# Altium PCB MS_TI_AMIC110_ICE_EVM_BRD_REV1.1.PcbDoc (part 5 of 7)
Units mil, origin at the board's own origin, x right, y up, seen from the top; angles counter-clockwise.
Board outline 3464.57 x 2204.72 mil, 8 copper layers (TopLayer - S1 (.GTL), MidLayer1 - S2 (.G1), MidLayer2 - S3 (.G2), MidLayer3 - S4 (.G3), MidLayer4 - S5 (.G4), MidLayer5 - S6 (.G5), MidLayer6 - S7 (.G6), BottomLayer - S8 (.GBL)), stack 58.937 mil thick; 504 components, 369 nets, 1811 pads, 874 vias.
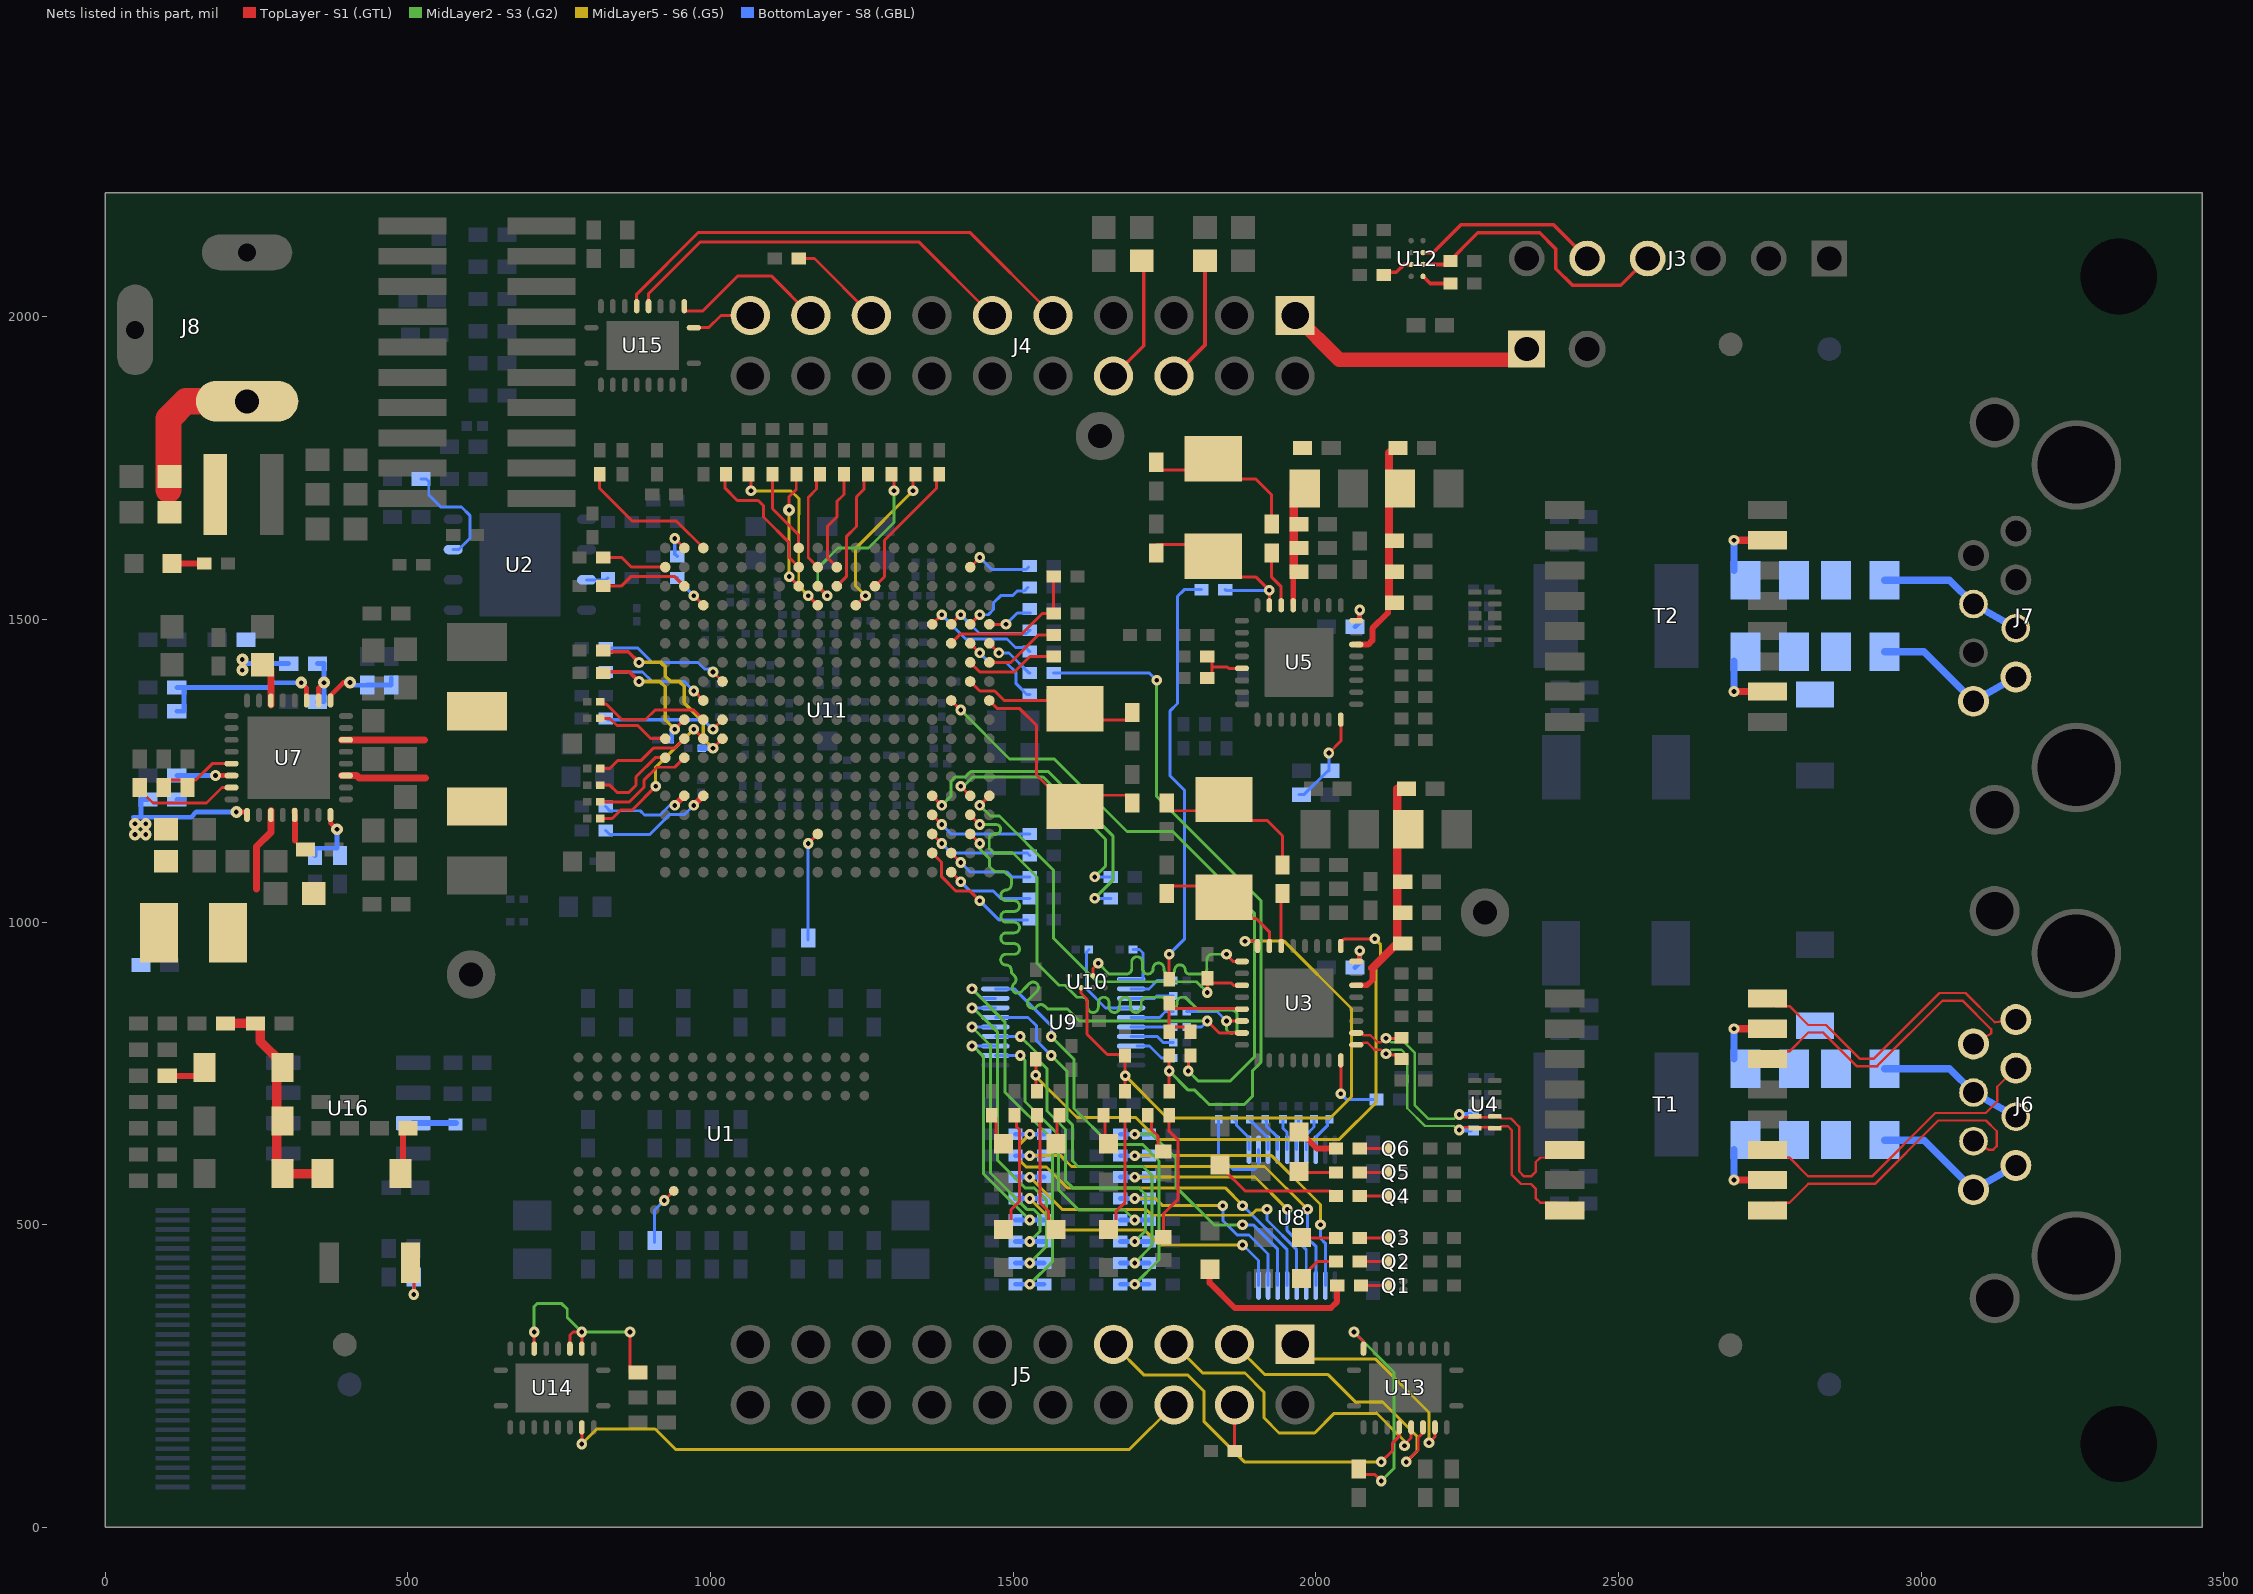
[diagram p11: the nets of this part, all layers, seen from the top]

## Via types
v1: diameter 17.72, hole 7.87, TopLayer - S1 (.GTL) to BottomLayer - S8 (.GBL), 746 vias
v2: diameter 19.68, hole 7.87, TopLayer - S1 (.GTL) to BottomLayer - S8 (.GBL), 128 vias

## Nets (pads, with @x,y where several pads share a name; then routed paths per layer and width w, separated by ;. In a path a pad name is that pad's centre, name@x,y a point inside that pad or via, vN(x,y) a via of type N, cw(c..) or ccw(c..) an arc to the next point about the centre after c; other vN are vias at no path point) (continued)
NetC36_1: C36.1 C37.1 C38.1 C39.1 R46.1 U3.14 | length 378.1
  TopLayer - S1 (.GTL) w9.45: U3.14@2066.93,895.67 2084.65,895.67 2093.5,904.53
  TopLayer - S1 (.GTL) w10: 2093.5,904.53 2093.5,924.21
  TopLayer - S1 (.GTL) w13.78: 2093.5,924.21 2134.84,965.55 2134.84,1015.75 2134.84,1220.47 R46.1@2149.61,1220.47
NetC45_1: C45.1 R50.2 Y1.1 | length 246.8
  TopLayer - S1 (.GTL) w4.92: C45.1@1753.94,1196.85 1753.94,1184.06 Y1.1@1839.57,1184.06 ; Y1.1@1848.43,1202.76 Y1.1@1858.27,1202.76 ; Y1.1@1865.16,1168.31 1919.29,1168.31 1944.88,1142.72 R50.2@1944.88,1094.49
NetC46_1: C46.1 U3.23 Y1.2 | length 232.4
  TopLayer - S1 (.GTL) w4.92: C46.1@1747.05,1060.04 Y1.2@1876.97,1060.04 ; Y1.2@1848.43,1041.34 Y1.2@1860.24,1041.34 ; Y1.2@1865.16,1005.91 1901.57,1005.91 1923.23,984.25 U3.23@1923.23,960.63
NetC55_1: C55.1 C56.1 C57.1 C58.1 R57.1 U5.21 | length 207
  TopLayer - S1 (.GTL) w9.45: U5.21@1962.6,1523.62 1962.6,1565.94
  TopLayer - S1 (.GTL) w13.78: C58.1@1972.44,1574.8 1963.58,1574.8 1963.58,1712.6 C55.1@1981.65,1712.6
NetC63_1: C63.1 C64.1 C65.1 C66.1 R62.1 U5.14 | length 363.4
  TopLayer - S1 (.GTL) w10: U5.14@2066.93,1458.66 2086.61,1458.66 2093.5,1465.55 2093.5,1485.24 2119.09,1510.83 2119.09,1516.73 C66.1@2129.92,1527.56
  TopLayer - S1 (.GTL) w13.78: R62.1@2121.06,1775.59 2121.06,1527.56 C66.1@2129.92,1527.56
NetC68_1: C68.1 R70.2 Y2.1 | length 264
  TopLayer - S1 (.GTL) w4.92: C68.1@1736.22,1759.84 1736.22,1747.05 Y2.1@1821.85,1747.05 ; Y2.1@1830.71,1765.75 Y2.1@1864.67,1731.79 ; Y2.1@1868.6,1731.79 1901.08,1731.79 1927.17,1705.71 R70.2@1927.17,1657.48
NetC69_2: C69.2 R74.1 U5.23 Y2.2 | length 374.7
  TopLayer - S1 (.GTL) w4.92: C69.2@1736.22,1610.24 1736.22,1623.72 1858.56,1623.72 Y2.2@1859.25,1623.03 ; Y2.2@1843.5,1604.33 Y2.2@1830.71,1604.33 1845.47,1589.57 1845.47,1569.88 1901.57,1569.88 v1(1923.23,1548.23) U5.23@1923.23,1523.62
  BottomLayer - S8 (.GBL) w4.92: R74.1@1850.39,1549.21 1851.38,1548.23 v1(1923.23,1548.23)
NetC72_2: C72.2 R80.2 U7.29 | length 48.9
  TopLayer - S1 (.GTL) w10: U7.29@312.99,1184.06 313.44,1174.5 313.44,1135.34 313.31,1135.22
NetC74_1: C74.1 C75.1 L2.2 R81.1 R82.2 U7.25 | length 232
  TopLayer - S1 (.GTL) w7.87: v2(216.54,1182.09) U7.25@233.27,1182.09
  BottomLayer - S8 (.GBL) w7.87: 46.26,1173.23 59.06,1173.23 ; R82.2@70.87,1202.76 59.06,1202.76 59.06,1173.23 ; v2(216.54,1182.09) 150.59,1182.09 141.73,1173.23 59.06,1173.23
  other v2: 49.21,1144.68 66.93,1144.68 49.21,1162.4 66.93,1162.4
NetC76_1: C76.1 D11.2 D12.1 D13.1 D14.1 R83.1 | length 386.4
  TopLayer - S1 (.GTL) w15.75: C76.1@198.82,832.68 R83.1@248.03,832.68 255.91,832.68 255.91,803.15 292.82,766.24 D12.1@292.82,759.84 D12.1@292.82,746.06 ; D14.1@282.97,581.69 D13.1@282.97,668.31 ; D13.1@282.97,671.26 D12.1@282.97,746.06 ; D14.1@292.82,584.65 D11.2@358.76,584.65
NetC87_1: C87.1 R98.1 R99.2 U7.14 | length 130.9
  TopLayer - S1 (.GTL) w11.81: U7.14@273.62,1359.25 U7.14@273.62,1366.14 C87.1@273.62,1419.29
  BottomLayer - S8 (.GBL) w7.87: v2@232.28,1427.17 R99.2@303.15,1427.17
  other v2: 226.38,1416.34 226.38,1434.06
NetC131_1: C131.1 U11.D9 | length 202
  TopLayer - S1 (.GTL) w4.92: v1(1003.94,1318.9) U11.D9@1019.68,1334.65
  BottomLayer - S8 (.GBL) w5.91: C131.1@830.71,1334.65 988.19,1334.65 v1(1003.94,1318.9)
NetC132_1: C132.1 U11.D11 | length 211.8
  TopLayer - S1 (.GTL) w4.92: v1(1003.94,1413.39) U11.D11@1019.68,1397.64
  BottomLayer - S8 (.GBL) w4.92: C132.1@830.71,1452.76 879.92,1452.76 903.54,1429.13 979.33,1429.13 990.16,1418.31 v1@999.02,1418.31
  BottomLayer - S8 (.GBL) w5.91: v1@999.02,1418.31 v1(1003.94,1413.39)
NetC133_1: C133.1 U11.C10 | length 176.4
  TopLayer - S1 (.GTL) w4.92: v1@972.92,1381.42 U11.C10@988.19,1366.14
  BottomLayer - S8 (.GBL) w4.92: C133.1@830.71,1413.39 887.8,1413.39 903.54,1397.64 956.69,1397.64 v1(972.44,1381.89)
NetC168_1: C168.1 U11.V10 Y3.2 | length 366.5
  TopLayer - S1 (.GTL) w4.92: U11.V10@1460.63,1366.14 1473.43,1353.35 1510.22,1353.35 1538.39,1325.18 1538.39,1243.11 1563.98,1217.52 Y3.2@1573.82,1217.52 ; Y3.2@1573.82,1209.65 C168.1@1696.85,1209.65 ; C168.1@1696.85,1196.85 C168.1@1696.85,1209.65 ; C168.1@1704.72,1209.65 C168.1@1696.85,1209.65
NetC170_1: C170.1 U11.U11 Y3.1 | length 307
  TopLayer - S1 (.GTL) w4.92: U11.U11@1429.13,1397.64 1444.88,1381.89 1469.49,1381.89 1485.24,1366.14 1588.58,1366.14 Y3.1@1602.36,1352.36 1621.06,1333.66 1696.85,1333.66 C170.1@1696.85,1346.46
NetC177_1: C177.1 C178.1 J8.1 L4.1 | length 259
  TopLayer - S1 (.GTL) w43.31: 104.33,1714.57 104.33,1831.69 133.21,1860.57 J8.1@234.25,1860.57
NetC182_1: C182.1 R182.2 U11.D8 | length 338.3
  TopLayer - S1 (.GTL) w4.92: v1(1003.95,1287.4) U11.D8@1019.68,1303.15
  TopLayer - S1 (.GTL) w5.91: R182.2@815.94,1446.85 864.17,1446.85 v1(881.89,1429.13)
  MidLayer5 - S6 (.G5) w5.91: v1(881.89,1429.13) 918.31,1429.13 925.2,1422.24 925.2,1406.5 934.06,1397.64 948.82,1397.64 956.69,1389.76 956.69,1362.2 988.19,1330.71 988.19,1303.16 v1(1003.95,1287.4)
  BottomLayer - S8 (.GBL) w9.84: C182.1@983.46,1287.4 C182.1@985.43,1287.4 v1(1003.95,1287.4)
NetC183_1: C183.1 R183.1 U11.B9 | length 230.7
  TopLayer - S1 (.GTL) w4.92: v1(940.94,1318.9) U11.B9@956.69,1334.65
  TopLayer - S1 (.GTL) w5.91: R183.1@822.83,1413.39 866.14,1413.39 v1(881.89,1397.64)
  MidLayer5 - S6 (.G5) w5.91: v1(881.89,1397.64) 916.34,1397.64 925.2,1388.78 925.2,1334.65 v1(940.94,1318.9)
  BottomLayer - S8 (.GBL) w7.87: C183.1@936.02,1299.21 v1@936.02,1318.7
NetC184_1: C184.1 R220.1 R221.1 R222.1 R223.1
NetC186_1: C186.1 R224.1 R225.1 R226.1 R227.1
NetD2_2: D2.2 R19.1 | length 203.7
  TopLayer - S1 (.GTL) w4.92: D2.2@1484.25,492.13 1496.06,503.94 1496.06,524.61 1510.83,539.37 1510.83,656.5 1505.91,661.42 1505.91,677.17 R19.1@1501.97,681.1
NetD3_2: D3.2 R20.1 | length 202.8
  TopLayer - S1 (.GTL) w4.92: R20.1@1537.4,681.1 1544.29,674.21 1544.29,536.42 1558.07,522.64 1558.07,504.92 D3.2@1570.87,492.13
NetD4_2: D4.2 R21.1 | length 200.4
  TopLayer - S1 (.GTL) w4.92: D4.2@1657.48,492.13 1670.28,504.92 1670.28,522.64 1685.04,537.4 R21.1@1685.04,681.1
NetD5_1: D5.1 R22.1 | length 218.1
  TopLayer - S1 (.GTL) w4.92: D5.1@1748.03,479.33 1748.03,517.72 1772.64,542.32 1772.64,639.76 1757.87,654.53 R22.1@1757.87,681.1
NetD6_1: D6.1 R26.1 | length 62.1
  TopLayer - S1 (.GTL) w4.92: D6.1@1972.19,588.51 1974.09,586.61 R26.1@2033.46,586.61
NetD7_2: D7.2 R28.2 | length 54.6
  TopLayer - S1 (.GTL) w4.92: R28.2@1466.54,681.1 1471.46,676.18 1471.46,646.65 D7.2@1484.25,633.86
NetD8_2: D8.2 R29.1 | length 48.1
  TopLayer - S1 (.GTL) w4.92: D8.2@1570.87,633.86 1572.83,635.83 R29.1@1572.83,681.1
NetD9_2: D9.2 R30.1 | length 49.7
  TopLayer - S1 (.GTL) w4.92: R30.1@1651.57,681.1 1651.57,639.76 D9.2@1657.48,633.86
NetD10_1: D10.1 R31.1 | length 70.6
  TopLayer - S1 (.GTL) w4.92: R31.1@1722.44,681.1 1728.35,675.2 1728.35,657.48 1739.17,646.65 1739.17,629.92 D10.1@1748.03,621.06
NetD11_1: D11.1 R84.1 | length 87.1
  TopLayer - S1 (.GTL) w9.84: D11.1@487.7,584.65 492.13,584.65 492.13,659.45 R84.1@500,659.45
NetD12_2: D12.2 R88.1 | length 75.3
  TopLayer - S1 (.GTL) w9.84: R88.1@102.36,746.06 163.88,746.06 D12.2@163.88,759.84
NetD15_2: D15.2 R178.1 | length 47.2
  TopLayer - S1 (.GTL) w9.84: D15.2@116.14,1592.52 R178.1@163.39,1592.52
NetD16_1: D16.1 R15.1 | length 281.3
  TopLayer - S1 (.GTL) w9.84: D16.1@1824.6,426.53 1824.6,404.12 1866.23,362.5 2024.86,362.5 2035.28,372.93 R15.1@2035.28,399.56
NetD17_1: D17.1 R16.1 | length 67.7
  TopLayer - S1 (.GTL) w4.92: D17.1@1976.5,412.95 2002.53,438.98 R16.1@2033.46,438.98
NetD18_1: D18.1 R17.1 | length 61.9
  TopLayer - S1 (.GTL) w4.92: D18.1@1971.97,479.43 1973.06,478.35 R17.1@2033.46,478.35
NetD19_1: D19.1 R25.1 | length 207.1
  TopLayer - S1 (.GTL) w4.92: D19.1@1845.54,593.5 1883.02,556.01 2024.7,556.01 R25.1@2033.46,547.24
NetD20_1: D20.1 R27.1 | length 72.6
  TopLayer - S1 (.GTL) w9.84: D20.1@1972.88,654.92 2001.81,625.98 R27.1@2033.46,625.98
NetJ3_4: J3.4 R172.2 U12.B1 | length 466.1
  TopLayer - S1 (.GTL) w5.91: U12.B1@2177.17,2086.61 2215.55,2086.61 2267.72,2138.78 2370.08,2138.78 2396.65,2112.2 2396.65,2079.72 2424.21,2052.17 2504.13,2052.17 J3.4@2548.43,2096.46
NetJ3_5: J3.5 U12.C1 | length 313.7
  TopLayer - S1 (.GTL) w5.91: U12.C1@2177.17,2106.3 2193.9,2106.3 2240.16,2152.56 2392.32,2152.56 J3.5@2448.43,2096.46
NetJ4_1: J4.1 J9.1 | length 420.3
  TopLayer - S1 (.GTL) w23.62: J4.1@1965.75,2002.36 2038.98,1929.13 2330.71,1929.13 J9.1@2348.43,1946.85
NetJ4_6: J4.6 R180.1 | length 211.4
  TopLayer - S1 (.GTL) w5.91: J4.6@1765.75,1902.36 1816.93,1953.54 R180.1@1816.93,2092.52
NetJ4_8: J4.8 R181.1 | length 212
  TopLayer - S1 (.GTL) w5.91: J4.8@1665.75,1902.36 1715.55,1952.17 1715.55,2089.57 R181.1@1712.6,2092.52
NetJ4_9: J4.9 U15.16 | length 806.8
  TopLayer - S1 (.GTL) w4.92: U15.16@877.95,2017.72 877.95,2037.4 980.31,2139.76 1428.35,2139.76 J4.9@1565.75,2002.36
NetJ4_11: J4.11 U15.15 | length 674.6
  TopLayer - S1 (.GTL) w4.92: U15.15@897.64,2017.72 897.64,2038.39 983.27,2124.02 1344.09,2124.02 J4.11@1465.75,2002.36
NetJ4_15: J4.15 R187.2 | length 159.1
  TopLayer - S1 (.GTL) w4.92: R187.2@1145.67,2096.46 1171.65,2096.46 J4.15@1265.75,2002.36
NetJ4_17: J4.17 U15.12 | length 268.1
  TopLayer - S1 (.GTL) w4.92: U15.12@956.69,2017.72 956.69,2009.84 987.2,2009.84 1045.28,2067.91 1100.2,2067.91 J4.17@1165.75,2002.36
NetJ4_19: J4.19 U15.11 | length 101.6
  TopLayer - S1 (.GTL) w4.92: U15.11@972.44,1982.28 997.05,1982.28 1017.13,2002.36 J4.19@1065.75,2002.36
NetJ5_1: J5.1 U13.18 | length 347.7
  TopLayer - S1 (.GTL) w4.92: v1(2187.01,139.76) 2196.85,149.61 U13.18@2196.85,165.35
  MidLayer5 - S6 (.G5) w4.92: J5.1@1965.75,302.36 1989.57,278.54 2098.43,278.54 2187.01,189.96 v1(2187.01,139.76)
NetJ5_3: J5.3 U13.17 | length 482.6
  TopLayer - S1 (.GTL) w4.92: v1(2149.61,108.27) 2169.29,127.95 2169.29,148.62 2177.17,156.5 U13.17@2177.17,165.35
  MidLayer5 - S6 (.G5) w4.92: J5.3@1865.75,302.36 1915.16,252.95 2019.69,252.95 2065.07,207.57 2110.34,207.57 2167.32,150.59 2167.32,125.98 v1(2149.61,108.27)
NetJ5_4: J5.4 R186.1 | length 100.2
  TopLayer - S1 (.GTL) w4.92: J5.4@1865.75,202.36 1865.75,126.38 R186.1@1866.14,125.98
  BottomLayer - S8 (.GBL) w4.92: J5.4@1865.75,178.74 J5.4@1865.75,202.36
NetJ5_5: J5.5 U13.16 | length 542.2
  TopLayer - S1 (.GTL) w4.92: v1(2146.72,134.71) 2146.72,136.88 2157.48,147.64 U13.16@2157.48,165.35
  MidLayer5 - S6 (.G5) w4.92: J5.5@1765.75,302.36 1813.19,254.92 1882.87,254.92 1914.37,223.43 1914.37,181.1 1939.32,156.15 1998.12,156.15 2030.45,188.48 2099.8,188.48 2100.19,188.87 2133.86,155.2 ; 2133.86,155.51 2146.72,142.65 v1(2146.72,134.71)
NetJ5_6: J5.6 U14.18 | length 1060.4
  TopLayer - S1 (.GTL) w4.68: v1(787.4,137.8) U14.18@787.4,165.35
  MidLayer5 - S6 (.G5) w4.92: v1(787.4,137.8) 812.01,162.4 908.46,162.4 941.93,128.94 1692.32,128.94 J5.6@1765.75,202.36
NetJ5_7: J5.7 U13.15 | length 621.6
  TopLayer - S1 (.GTL) w4.92: v1(2108.27,108.27) 2126.97,126.97 2126.97,139.76 2137.8,150.59 U13.15@2137.8,165.35
  MidLayer5 - S6 (.G5) w4.92: J5.7@1665.75,302.36 1716.54,251.57 1788.78,251.57 1814.96,225.39 1814.96,175.2 1881.89,108.27 v1(2108.27,108.27)
NetJ6_4: J6.4 J6.5 R220.2 | length 244.1
  BottomLayer - S8 (.GBL) w11.81: R220.2@2939.61,757.87 3047.24,757.87 J6.4@3086.61,718.5 J6.5@3156.69,678.35
NetJ6_7: J6.7 J6.8 R221.2 | length 261.7
  BottomLayer - S8 (.GBL) w11.81: R221.2@2939.61,639.76 3004.72,639.76 J6.8@3086.61,557.87 J6.7@3156.69,598.03
NetJ7_4: J7.4 J7.5 R224.2 | length 244.1
  BottomLayer - S8 (.GBL) w11.81: R224.2@2939.61,1564.96 3047.24,1564.96 J7.4@3086.61,1525.59 J7.5@3156.69,1485.43
NetJ7_7: J7.7 J7.8 R225.2 | length 261.7
  BottomLayer - S8 (.GBL) w11.81: R225.2@2939.61,1446.85 3004.72,1446.85 J7.8@3086.61,1364.96 J7.7@3156.69,1405.12
NetL1_1: L1.1 U7.6 | length 136.8
  TopLayer - S1 (.GTL) w11.81: U7.6@390.75,1301.18 U7.6@397.64,1301.18 527.56,1301.18
NetL2_1: L2.1 U7.27 | length 138.7
  TopLayer - S1 (.GTL) w11.81: 250,1055.12 250,1125 273.62,1148.62 U7.27@273.62,1177.17 U7.27@273.62,1184.05
NetL3_1: L3.1 U7.3 | length 139.4
  TopLayer - S1 (.GTL) w11.81: U7.3@390.75,1242.13 U7.3@397.64,1242.13 415.35,1242.13 419.29,1238.19 528.54,1238.19
NetQ1_3: Q1.3 R15.2 | length 46.3
  TopLayer - S1 (.GTL) w4.92: R15.2@2074.8,399.61 Q1.3@2119.09,399.61 Q1.3@2121.06,399.61
NetQ2_3: Q2.3 R16.2 | length 46.3
  TopLayer - S1 (.GTL) w4.92: R16.2@2074.8,438.98 Q2.3@2119.09,438.98 Q2.3@2121.06,438.98
NetQ3_3: Q3.3 R17.2 | length 46.3
  TopLayer - S1 (.GTL) w4.92: R17.2@2074.8,478.35 Q3.3@2119.09,478.35 Q3.3@2121.06,478.35
NetQ4_3: Q4.3 R25.2 | length 46.3
  TopLayer - S1 (.GTL) w4.92: R25.2@2072.83,547.24 Q4.3@2119.09,547.24
NetQ5_3: Q5.3 R26.2 | length 46.3
  TopLayer - S1 (.GTL) w4.92: R26.2@2072.83,586.61 Q5.3@2119.09,586.61
NetQ6_3: Q6.3 R27.2 | length 46.3
  TopLayer - S1 (.GTL) w4.92: R27.2@2072.83,625.98 Q6.3@2119.09,625.98
NetR10_2: R10.2 S1.2 | length 86.6
  TopLayer - S1 (.GTL) w4.92: S1.2@503.94,437.01 509.84,437.01 v1(509.84,384.84)
  BottomLayer - S8 (.GBL) w5.91: v1(509.84,384.84) R10.2@509.84,413.39
NetR38_1: R38.1 U1.L8 | length 98.5
  TopLayer - S1 (.GTL) w4.92: v1(923.42,540.15) U1.L8@939.17,555.9
  BottomLayer - S8 (.GBL) w4.92: R38.1@907.67,470.4 R38.1@907.67,474.02 907.67,524.4 v1(923.42,540.15)
NetR39_1: R39.1 U2.3 | length 36.8
  BottomLayer - S8 (.GBL) w4.92: U2.3@795.28,1565.55 827.36,1565.55 R39.1@830.71,1568.9
NetR40_1: R40.1 U2.7 | length 192.4
  BottomLayer - S8 (.GBL) w4.92: R40.1@521.65,1732.28 530.51,1732.28 534.45,1728.35 534.45,1705.71 554.13,1686.02 588.58,1686.02 602.36,1672.24 602.36,1633.86 584.06,1615.55 U2.7@574.8,1615.55
NetR47_1: R47.1 U3.16 | length 53.5
  TopLayer - S1 (.GTL) w7.87: U3.16@2066.93,935.04 2071.85,935.04 v1@2071.85,952.76
  BottomLayer - S8 (.GBL) w7.87: R47.1@2064.96,925.2 2072.83,933.07 v1(2072.83,952.76)
NetR48_2: R48.2 U3.8 | length 118.3
  TopLayer - S1 (.GTL) w4.92: v1(2041.34,716.54) U3.8@2041.34,771.65
  BottomLayer - S8 (.GBL) w4.92: v1(2041.34,716.54) 2051.18,706.69 R48.2@2100.39,706.69
NetR50_1: R50.1 U3.22 | length 87.4
  TopLayer - S1 (.GTL) w4.92: U3.22@1942.91,960.63 1942.91,1045.28 R50.1@1944.88,1047.24
NetR51_2: R51.2 R52.2 R54.2 U3.29 | length 202.2
  TopLayer - S1 (.GTL) w4.92: R51.2@1757.87,818.9 R51.2@1757.87,826.77 ; R52.2@1793.31,818.9 1793.31,826.77 R51.2@1757.87,826.77 ; U3.29@1877.95,856.3 1876.97,857.28 1757.87,857.28 R51.2@1757.87,826.77
NetR63_1: R63.1 U5.16 | length 53.1
  TopLayer - S1 (.GTL) w7.87: U5.16@2066.93,1498.03 2071.85,1498.03 v1@2071.85,1515.75
  BottomLayer - S8 (.GBL) w7.87: R63.1@2064.96,1488.19 2071.85,1495.08 v1@2071.85,1515.75
  other v1: 2072.83,1515.75
NetR64_1: R64.1 R65.1 U5.8 | length 159.1
  TopLayer - S1 (.GTL) w4.92: v1(2021.65,1279.53) 2041.34,1299.21 U5.8@2041.34,1334.65
  BottomLayer - S8 (.GBL) w4.92: R64.1@1972.44,1210.63 R64.1@1976.38,1210.63 1980.31,1210.63 R65.1@2021.65,1251.97 ; R65.1@2021.65,1250 R65.1@2021.65,1251.97 ; v1(2021.65,1279.53) R65.1@2021.65,1251.97
NetR70_1: R70.1 U5.22 | length 93.1
  TopLayer - S1 (.GTL) w4.92: R70.1@1927.17,1610.24 1927.17,1569.88 1942.91,1554.13 U5.22@1942.91,1523.62
NetR71_2: R71.2 R73.2 U5.29 | length 103.2
  TopLayer - S1 (.GTL) w4.92: R71.2@1820.87,1403.54 1828.74,1403.54 1828.74,1421.26 ; R73.2@1820.87,1440.94 1828.74,1440.94 1828.74,1421.26 ; U5.29@1877.95,1419.29 1856.3,1419.29 1854.33,1421.26 1828.74,1421.26
NetR78_1: R78.1 R79.2 U7.9 | length 125
  TopLayer - S1 (.GTL) w7.87: U7.9@372.05,1366.14 372.05,1374.42 393.63,1396 v2(404.51,1396)
  BottomLayer - S8 (.GBL) w7.87: v2@409.04,1391.49 432.58,1391.49 432.82,1391.73 R79.2@472.44,1391.73 R79.2@472.44,1403.54
NetR82_1: R82.1 R86.2 U7.22 | length 143.8
  TopLayer - S1 (.GTL) w4.92: U7.22@208.66,1240.16 U7.22@208.66,1242.13
  TopLayer - S1 (.GTL) w7.87: v1(182.09,1242.25) 208.53,1242.25 U7.22@208.66,1242.13
  BottomLayer - S8 (.GBL) w7.87: R82.1@118.11,1202.76 129.92,1202.76 R86.2@129.92,1242.13 ; R86.2@118.11,1242.13 R86.2@129.92,1242.13 ; v1(182.09,1242.25) 130.05,1242.25 R86.2@129.92,1242.13
NetR90_1: R90.1 R92.2 U7.32 | length 107.8
  TopLayer - S1 (.GTL) w7.87: U7.32@372.05,1177.17 372.05,1164.37 v2(382.87,1153.54)
  BottomLayer - S8 (.GBL) w7.87: R92.2@346.46,1110.24 346.46,1122.05 382.87,1122.05 v2(382.87,1153.54)
NetR93_2: R93.2 U7.23 | length 175.1
  TopLayer - S1 (.GTL) w4.92: R93.2@57.09,1222.44 57.09,1218.5 78.74,1196.85 167.32,1196.85 192.91,1222.44 U7.23@208.66,1222.44
NetR96_1: R96.1 R97.2 U7.11 | length 293.3
  TopLayer - S1 (.GTL) w7.87: v2(323.82,1395.67) 332.68,1386.81 U7.11@332.68,1366.14
  BottomLayer - S8 (.GBL) w7.87: R97.2@118.11,1348.43 129.92,1348.43 R96.1@129.92,1387.8 ; R96.1@118.11,1387.8 R96.1@129.92,1387.8 ; v2(323.82,1395.67) 277.56,1395.67 269.69,1387.8 R96.1@129.92,1387.8
NetR99_1: R99.1 R100.2 U7.10 | length 117.8
  TopLayer - S1 (.GTL) w7.87: U7.10@352.36,1366.14 352.36,1386.81 v2(361.22,1395.67)
  BottomLayer - S8 (.GBL) w7.87: R100.2@350.39,1364.17 361.22,1364.17 v2(361.22,1395.67) 361.22,1427.17 R99.1@350.39,1427.17
NetR101_1: R101.1 R102.1 U7.21 | length 136
  TopLayer - S1 (.GTL) w4.92: R102.1@96.46,1222.44 96.46,1235.24 150.06,1235.24 176.64,1261.81 U7.21@208.66,1261.81
NetR103_1: R103.1 R122.2 U9.8 | length 650.9
  MidLayer2 - S3 (.G2) w4.92: v1(1432.09,889.76) 1486.22,835.63 1486.22,719.49 1564.96,640.75 1564.96,438.98 v1(1527.56,401.57)
  BottomLayer - S8 (.GBL) w4.92: v1(1432.09,889.76) 1447.83,874.02 U9.8@1470.47,874.02
  BottomLayer - S8 (.GBL) w7.87: R103.1@1503.94,401.57 v1(1527.56,401.57) R122.2@1551.18,401.57
NetR104_1: R104.1 R123.2 U9.9 | length 714.4
  MidLayer2 - S3 (.G2) w4.92: v1(1562.99,811.02) 1600.39,773.62 1600.39,691.93 1659.45,632.87 1713.58,632.87 1741.14,605.32 1741.14,441.93 v1(1700.79,401.57)
  BottomLayer - S8 (.GBL) w4.92: U9.9@1470.47,889.76 1501.97,889.76 1562.99,828.74 v1(1562.99,811.02)
  BottomLayer - S8 (.GBL) w7.87: R123.2@1677.17,401.57 v1(1700.79,401.57) R104.1@1724.41,401.57
NetR105_1: R105.1 R124.2 U9.7 | length 575.1
  MidLayer2 - S3 (.G2) w4.92: v1@1434.06,858.27 1474.41,817.91 1474.41,606.3 1519.69,561.02 1534.45,561.02 1555.12,540.35 1555.12,464.57 v1(1527.56,437.01)
  BottomLayer - S8 (.GBL) w4.92: v1@1434.06,858.27 U9.7@1470.47,858.27
  BottomLayer - S8 (.GBL) w7.87: R105.1@1503.94,437.01 v1(1527.56,437.01) R124.2@1551.18,437.01
  other v1: 1432.09,858.27
NetR106_1: R106.1 R125.2 U9.6 | length 666.4
  MidLayer2 - S3 (.G2) w4.92: v1(1562.99,779.53) 1588.58,753.94 1588.58,674.21 1598.43,664.37 1598.43,605.32 1607.28,596.46 1714.57,596.46 1729.33,581.69 1729.33,465.55 v1(1700.79,437.01)
  BottomLayer - S8 (.GBL) w4.92: U9.6@1470.47,842.52 1524.61,842.52 1538.88,828.25 1538.88,803.64 v1(1562.99,779.53)
  BottomLayer - S8 (.GBL) w7.87: R125.2@1677.17,437.01 v1(1700.79,437.01) R106.1@1724.41,437.01
NetR107_1: R107.1 R126.2 U9.5 | length 499.7
  MidLayer2 - S3 (.G2) w4.92: v1(1432.09,826.77) 1462.6,796.26 1462.6,585.63 1522.64,525.59 1533.46,525.59 1544.29,514.76 1544.29,489.17 v1(1527.56,472.44)
  BottomLayer - S8 (.GBL) w4.92: v1(1432.09,826.77) U9.5@1470.47,826.77
  BottomLayer - S8 (.GBL) w7.87: R107.1@1503.94,472.44 v1(1527.56,472.44) R126.2@1551.18,472.44
NetR108_1: R108.1 R127.2 U9.4 | length 584.1
  MidLayer2 - S3 (.G2) w4.92: v1(1511.81,811.02) 1538.39,784.45 1538.39,775.59 1556.1,757.87 1556.1,687.99 1586.61,657.48 1586.61,572.83 1598.43,561.02 1707.68,561.02 1718.5,550.2 1718.5,490.16 v1(1700.79,472.44)
  BottomLayer - S8 (.GBL) w4.92: U9.4@1470.47,811.02 v1(1511.81,811.02)
  BottomLayer - S8 (.GBL) w7.87: R127.2@1677.17,472.44 v1(1700.79,472.44) R108.1@1724.41,472.44
NetR109_1: R109.1 R128.2 U9.3 | length 409.8
  MidLayer2 - S3 (.G2) w4.92: v1@1434.06,795.28 1450.79,778.54 1450.79,584.65 v1(1527.56,507.87)
  BottomLayer - S8 (.GBL) w4.92: v1@1434.06,795.28 U9.3@1470.47,795.28
  BottomLayer - S8 (.GBL) w7.87: R109.1@1503.94,507.87 v1(1527.56,507.87) R128.2@1551.18,507.87
  other v1: 1432.09,795.28
NetR110_1: R110.1 R129.2 U9.2 | length 482.9
  MidLayer2 - S3 (.G2) w4.92: v1(1511.81,779.53) 1519.69,771.65 1519.69,703.74 1574.8,648.62 1574.8,558.07 1608.27,524.61 1684.06,524.61 v1(1700.79,507.87)
  BottomLayer - S8 (.GBL) w4.92: U9.2@1470.47,779.53 v1(1511.81,779.53)
  BottomLayer - S8 (.GBL) w7.87: R129.2@1677.17,507.87 v1(1700.79,507.87) R110.1@1724.41,507.87
NetR111_1: R111.1 R130.2 U8.9 | length 508.9
  MidLayer5 - S6 (.G5) w4.92: v1(1527.56,543.31) 1579.72,491.14 1717.52,491.14 1742.13,466.54 v1@1879.92,466.54
  BottomLayer - S8 (.GBL) w4.92: v1@1879.92,466.54 1905.51,440.94 U8.9@1905.51,399.61
  BottomLayer - S8 (.GBL) w7.87: R111.1@1503.94,543.31 v1(1527.56,543.31) R130.2@1551.18,543.31
  other v1: 1878.75,466.73
NetR112_1: R112.1 R131.2 U8.8 | length 372.8
  MidLayer5 - S6 (.G5) w4.92: v1(1700.79,543.31) 1736.22,543.31 1736.22,542.32 1747.05,531.5 v1(1846.46,531.5)
  BottomLayer - S8 (.GBL) w4.92: v1(1846.46,531.5) 1846.46,506.89 1870.08,483.27 1889.76,483.27 1921.26,451.77 U8.8@1921.26,399.61
  BottomLayer - S8 (.GBL) w7.87: R131.2@1677.17,543.31 v1(1700.79,543.31) R112.1@1724.41,543.31
NetR113_1: R113.1 R132.2 U8.5 | length 613.1
  MidLayer5 - S6 (.G5) w4.92: v1(1527.56,578.74) 1580.71,525.59 1719.49,525.59 1729.33,515.75 1892.72,515.75 1901.57,524.61 v1@1917.32,524.61
  BottomLayer - S8 (.GBL) w4.92: v1(1919.29,525.59) 1919.29,507.87 1968.5,458.66 U8.5@1968.5,399.61
  BottomLayer - S8 (.GBL) w7.87: R113.1@1503.94,578.74 v1(1527.56,578.74) R132.2@1551.18,578.74
NetR114_1: R114.1 R133.2 U8.4 | length 460.3
  MidLayer5 - S6 (.G5) w4.92: v1(1700.79,578.74) 1899.61,578.74 v1(1952.76,525.59)
  BottomLayer - S8 (.GBL) w4.92: v1(1952.76,525.59) 1952.76,490.16 1984.25,458.66 U8.4@1984.25,399.61
  BottomLayer - S8 (.GBL) w7.87: R133.2@1677.17,578.74 v1(1700.79,578.74) R114.1@1724.41,578.74
NetR115_1: R115.1 R134.2 U8.3 | length 674.3
  MidLayer5 - S6 (.G5) w4.92: v1(1527.56,614.17) 1578.74,614.17 1596.46,596.46 1915.35,596.46 v1(1986.22,525.59)
  BottomLayer - S8 (.GBL) w4.92: v1(1986.22,525.59) 1986.22,478.35 2000,464.57 U8.3@2000,399.61
  BottomLayer - S8 (.GBL) w7.87: R115.1@1503.94,614.17 v1(1527.56,614.17) R134.2@1551.18,614.17
NetR116_1: R116.1 R135.2 U8.2 | length 524.9
  MidLayer5 - S6 (.G5) w4.92: v1(1700.79,614.17) 1927.17,614.17 2007.87,533.46 v1(2007.87,500)
  BottomLayer - S8 (.GBL) w4.92: v1(2007.87,500) 2007.87,477.36 2015.75,469.49 U8.2@2015.75,399.61
  BottomLayer - S8 (.GBL) w7.87: R135.2@1677.17,614.17 v1(1700.79,614.17) R116.1@1724.41,614.17
NetR117_1: R117.1 R136.2 U8.6 | length 659.6
  MidLayer5 - S6 (.G5) w4.92: v1(1527.56,649.61) 1510.83,632.87 1510.83,606.3 1521.65,595.47 1555.12,595.47 1589.57,561.02 1850.39,561.02 v1@1879.92,531.5
  BottomLayer - S8 (.GBL) w4.92: v1@1879.92,531.5 1952.76,458.66 U8.6@1952.76,399.61
  BottomLayer - S8 (.GBL) w7.87: R117.1@1503.94,649.61 v1(1527.56,649.61) R136.2@1551.18,649.61
  other v1: 1878.75,531.5
NetR118_1: R118.1 R137.2 U8.7 | length 449.9
  MidLayer2 - S3 (.G2) w4.92: v1(1700.79,649.61) 1729.33,649.61 1768.7,610.24 1768.7,562.99 1831.69,500 v1@1879.92,500
  BottomLayer - S8 (.GBL) w4.92: v1@1879.92,500 1896.65,500 1937.01,459.65 U8.7@1937.01,399.61
  BottomLayer - S8 (.GBL) w7.87: R137.2@1677.17,649.61 v1(1700.79,649.61) R118.1@1724.41,649.61
  other v1: 1878.75,500
NetR139_1: R139.1 U11.K17 | length 159.7
  TopLayer - S1 (.GTL) w4.92: U11.K17@1208.66,1586.61 1192.91,1602.36 1192.91,1653.54 1208.66,1669.29 1208.66,1694.88 1220.47,1706.69 R139.1@1220.47,1728.35
NetR140_1: R140.1 U11.K16 | length 206.2
  TopLayer - S1 (.GTL) w4.92: U11.K16@1208.66,1555.12 1224.41,1570.87 1224.41,1636.81 1241.14,1653.54 1241.14,1702.76 1253.94,1715.55 1253.94,1734.25 R140.1@1259.84,1740.16
NetR141_2: R141.2 U11.C5 | length 190.8
  TopLayer - S1 (.GTL) w10: v1(972.44,1192.91) U11.C5@988.19,1208.66
  BottomLayer - S8 (.GBL) w4.92: R141.2@826.77,1151.57 833.66,1144.68 899.61,1144.68 932.58,1177.66 957.18,1177.66 v1(972.44,1192.91)
NetR142_2: R142.2 U11.B5 | length 148.7
  TopLayer - S1 (.GTL) w10: v1(940.94,1192.91) U11.B5@956.69,1208.66
  BottomLayer - S8 (.GBL) w4.92: R142.2@826.77,1190.94 833.66,1184.06 883.86,1184.06 890.75,1177.17 916.34,1177.17 932.09,1192.91 v1(940.94,1192.91)
NetR143_1: R143.1 U11.J16 | length 312.8
  TopLayer - S1 (.GTL) w4.68: R143.1@1299.21,1740.16 1303.15,1736.22 v1(1303.15,1712.6)
  TopLayer - S1 (.GTL) w4.92: U11.J16@1177.17,1555.12 v1(1192.91,1539.37)
  MidLayer2 - S3 (.G2) w4.92: v1(1192.91,1539.37) 1177.17,1555.12 1177.17,1584.65 1210.63,1618.11 1260.83,1618.11 1303.15,1660.43 v1(1303.15,1712.6)
NetR144_1: R144.1 U11.H17 | length 224.3
  TopLayer - S1 (.GTL) w4.92: R144.1@1023.62,1740.16 1023.62,1717.52 1044.29,1696.85 1078.74,1696.85 1087.6,1687.99 1087.6,1669.29 1129.92,1626.97 1129.92,1602.36 U11.H17@1145.67,1586.61
NetR145_1: R145.1 U11.H16 | length 196.5
  TopLayer - S1 (.GTL) w4.68: v2(1129.92,1681.1) 1129.92,1702.76 1141.73,1714.57 R145.1@1141.73,1740.16
  TopLayer - S1 (.GTL) w4.92: v1(1129.92,1570.87) U11.H16@1145.68,1555.12
  MidLayer5 - S6 (.G5) w4.92: v1(1129.92,1570.87) v2(1129.92,1681.1)
NetR146_1: R146.1 U11.L15 | length 271.1
  TopLayer - S1 (.GTL) w4.68: v1(1334.65,1712.6) 1334.65,1736.22 R146.1@1338.58,1740.16
  TopLayer - S1 (.GTL) w4.92: U11.L15@1240.18,1523.64 v1(1255.9,1539.37)
  MidLayer5 - S6 (.G5) w4.92: v1(1255.9,1539.37) 1239.17,1556.1 1239.17,1617.13 v1(1334.65,1712.6)
NetR147_1: R147.1 U11.J15 | length 302.8
  TopLayer - S1 (.GTL) w4.68: R147.1@1062.99,1740.16 1066.93,1736.22 v1(1066.93,1712.6)
  TopLayer - S1 (.GTL) w4.92: v1(1161.42,1539.37) U11.J15@1177.17,1523.62
  MidLayer5 - S6 (.G5) w4.68: v1(1066.93,1712.6) 1132.87,1712.6 1146.04,1699.43 1146.04,1674.05 1145.67,1673.68 1145.67,1555.12 v1(1161.42,1539.37)
NetR148_1: R148.1 U11.J17 | length 168.2
  TopLayer - S1 (.GTL) w4.68: U11.J17@1177.17,1586.61 1161.42,1602.36 1161.42,1701.77 1175.2,1715.55 1175.2,1734.25 R148.1@1181.1,1740.16
NetR149_2: R149.2 U11.A17 | length 108.9
  TopLayer - S1 (.GTL) w4.92: R149.2@822.83,1602.36 853.35,1602.36 869.09,1586.61 U11.A17@925.2,1586.61
NetR150_2: R150.2 U11.V12 | length 125.1
  TopLayer - S1 (.GTL) w4.92: U11.V12@1460.63,1429.13 1496.06,1429.13 1541.34,1474.41 R150.2@1566.93,1474.41
NetR151_1: R151.1 U11.H18 | length 140
  TopLayer - S1 (.GTL) w4.92: R151.1@1102.36,1740.16 1102.36,1683.07 1145.67,1639.76 U11.H18@1145.67,1618.11
NetR152_2: R152.2 U11.B16 | length 146.9
  TopLayer - S1 (.GTL) w4.92: R152.2@822.83,1555.12 852.36,1555.12 868.11,1570.87 940.94,1570.87 U11.B16@956.69,1555.12
NetR153_2: R153.2 R155.1 U11.T13 | length 250.7
  TopLayer - S1 (.GTL) w4.92: U11.T13@1397.64,1460.63 1413.39,1476.38 1514.76,1476.38 1548.23,1509.84 R153.2@1566.93,1509.84 R155.1@1566.93,1570.87
NetR154_1: R154.1 U11.R2 | length 217
  TopLayer - S1 (.GTL) w4.92: U11.R2@1366.14,1114.17 1381.89,1098.43 1381.89,1074.8 1405.51,1051.18 1429.13,1051.18 v1(1444.88,1035.43)
  BottomLayer - S8 (.GBL) w4.92: v1(1444.88,1035.43) 1476.38,1003.94 R154.1@1523.62,1003.94
NetR156_1: R156.1 U11.R3 | length 176.1
  TopLayer - S1 (.GTL) w4.92: U11.R3@1366.14,1145.67 v1(1381.89,1129.92)
  BottomLayer - S8 (.GBL) w4.92: v1(1381.89,1129.92) 1397.64,1114.17 1523.62,1114.17 R156.1@1527.56,1110.24
NetR157_1: R157.1 U11.R4 | length 174.4
  TopLayer - S1 (.GTL) w4.92: U11.R4@1366.14,1177.17 v1(1381.89,1161.42)
  BottomLayer - S8 (.GBL) w4.92: v1(1381.89,1161.42) 1397.64,1145.67 R157.1@1527.56,1145.67
NetR158_1: R158.1 U11.T1 | length 147.9
  TopLayer - S1 (.GTL) w4.92: U11.T1@1397.64,1082.68 v1(1413.39,1066.93)
  BottomLayer - S8 (.GBL) w4.92: v1(1413.39,1066.93) 1429.13,1051.18 1467.52,1051.18 1479.33,1039.37 R158.1@1527.56,1039.37
NetR159_1: R159.1 U11.T2 | length 146.2
  TopLayer - S1 (.GTL) w4.92: U11.T2@1397.64,1114.17 v1(1413.39,1098.43)
  BottomLayer - S8 (.GBL) w4.92: v1(1413.39,1098.43) 1429.13,1082.68 1490.16,1082.68 1498.03,1074.8 R159.1@1527.56,1074.8
NetR160_1: R160.1 U11.U17 | length 118.8
  TopLayer - S1 (.GTL) w4.92: U11.U17@1429.13,1586.61 1429.59,1586.61 v1@1445.4,1602.43 ; v1@1439.53,1602.37 v1(1444.92,1602.37)
  BottomLayer - S8 (.GBL) w4.92: v1(1444.92,1602.37) 1464.72,1582.57 1521.54,1582.57 R160.1@1525.59,1586.61
NetR161_2: R161.2 U11.V13 | length 87.3
  TopLayer - S1 (.GTL) w4.92: U11.V13@1460.63,1460.63 v1(1476.41,1444.87)
  BottomLayer - S8 (.GBL) w4.92: v1(1476.41,1444.87) 1493.12,1444.87 1526.57,1411.42 R161.2@1527.56,1411.42
NetR163_2: R163.2 U11.U13 | length 144.4
  TopLayer - S1 (.GTL) w4.92: U11.U13@1429.13,1460.63 v1(1444.92,1444.87)
  BottomLayer - S8 (.GBL) w4.92: v1(1444.92,1444.87) 1460.66,1429.13 1488.19,1429.13 1504.92,1412.4 1504.92,1393.7 1522.64,1375.98 R163.2@1527.56,1375.98
NetR164_1: R164.1 U11.V14 | length 75.7
  TopLayer - S1 (.GTL) w4.92: U11.V14@1460.63,1492.13 v1(1488.19,1492.13)
  BottomLayer - S8 (.GBL) w4.92: v1(1488.19,1492.13) 1506.89,1510.83 R164.1@1528.54,1510.83
NetR165_1: R165.1 U11.U14 | length 127.1
  TopLayer - S1 (.GTL) w4.92: U11.U14@1429.13,1492.13 v1(1444.91,1507.9)
  BottomLayer - S8 (.GBL) w4.92: v1(1444.91,1507.9) 1458.68,1507.9 1467.52,1516.73 1467.52,1527.56 1479.33,1539.37 1498.82,1539.37 1506.3,1546.85 1518.31,1546.85 R165.1@1524.61,1553.15
NetR166_1: R166.1 U11.T14 | length 151.8
  TopLayer - S1 (.GTL) w4.92: U11.T14@1397.64,1492.13 1401.58,1496.06 1401.58,1496.46 1409.06,1503.93 1409.45,1503.93 v1(1413.39,1507.87)
  BottomLayer - S8 (.GBL) w4.92: v1(1413.39,1507.87) 1444.44,1476.87 1522.15,1476.87 R166.1@1527.56,1482.28
NetR167_1: R167.1 U11.R14 | length 193.3
  TopLayer - S1 (.GTL) w4.92: U11.R14@1366.14,1492.13 1370.09,1496.07 1370.09,1496.12 1377.92,1503.95 1377.97,1503.95 v1(1381.89,1507.87)
  BottomLayer - S8 (.GBL) w4.92: v1(1381.89,1507.87) 1421.8,1468.01 1489.67,1468.01 1503.94,1453.74 1520.67,1453.74 R167.1@1527.56,1446.85
NetR169_2: R169.2 U11.J3 | length 181.8
  TopLayer - S1 (.GTL) w4.92: v1(1161.42,1129.92) U11.J3@1177.17,1145.67
  BottomLayer - S8 (.GBL) w4.92: R169.2@1161.42,970.4 R169.2@1161.42,974.02 v1(1161.42,1129.92)
NetR170_2: R170.2 U12.A1 | length 50.2
  TopLayer - S1 (.GTL) w5.91: U12.A1@2177.17,2066.93 2188.98,2055.12 R170.2@2222.44,2055.12
NetR171_2: R171.2 U12.B2 | length 52.6
  TopLayer - S1 (.GTL) w5.91: R171.2@2112.2,2068.9 2117.13,2073.82 2132.87,2073.82 2145.67,2086.61 U12.B2@2157.48,2086.61
NetR176_2: R176.2 U13.9 | length 360.9
  TopLayer - S1 (.GTL) w4.92: v1(2062.99,322.83) 2078.74,307.09 U13.9@2078.74,295.28 ; R176.2@2067.91,87.6 2097.44,87.6 v1(2108.27,76.77)
  MidLayer2 - S3 (.G2) w4.92: v1(2062.99,322.83) 2128.94,256.89 2128.94,97.44 v1(2108.27,76.77)
NetR177_2: R177.2 U14.3 U14.4 U14.7 | length 408
  TopLayer - S1 (.GTL) w4.68: U14.3@787.4,295.28 v1(787.4,322.83)
  TopLayer - S1 (.GTL) w4.92: U14.7@708.66,295.28 v1(708.66,322.83) ; U14.4@767.72,295.28 767.72,317.91 772.64,322.83 v1(787.4,322.83) ; v1(867.13,322.83) 867.13,255.91 R177.2@879.92,255.91
  MidLayer2 - S3 (.G2) w4.92: v1(708.66,322.83) 708.66,364.87 713.38,369.59 754.35,369.59 763.29,360.65 763.29,348.01 ; 763.29,346.95 v1(787.4,322.83) v1(867.13,322.83)
NetR179_1: R179.1 U11.M16 | length 229.1
  TopLayer - S1 (.GTL) w4.92: U11.M16@1271.65,1555.12 1287.4,1570.87 1287.4,1630.91 1373.03,1716.54 1373.03,1735.24 R179.1@1377.95,1740.16
NetR190_1: R190.1 U16.7 | length 70.3
  BottomLayer - S8 (.GBL) w10: U16.7@508.86,667.91 578.74,667.91 R190.1@579.13,667.91
NetR191_1: R191.1 U8.18 | length 59.4
  BottomLayer - S8 (.GBL) w4.92: U8.18@2000,624.02 2000,644.68 2019.69,664.37 2019.69,671.06 R191.1@2022.64,674.02
NetR192_1: R192.1 U8.17 | length 55.3
  BottomLayer - S8 (.GBL) w4.92: U8.17@1984.25,624.02 1984.25,648.62 1997.05,661.42 R192.1@1997.05,674.02
NetR193_1: R193.1 U8.16 | length 51.2
  BottomLayer - S8 (.GBL) w4.92: U8.16@1968.5,624.02 1968.5,651.57 1971.46,654.53 R193.1@1971.46,674.02
NetR194_1: R194.1 U8.15 | length 52.9
  BottomLayer - S8 (.GBL) w4.92: R194.1@1945.87,674.02 1945.87,659.45 1952.76,652.56 U8.15@1952.76,624.02
NetR195_1: R195.1 U8.14 | length 58.6
  BottomLayer - S8 (.GBL) w4.92: R195.1@1916.34,674.02 1918.31,672.05 1918.31,663.39 1937.01,644.69 U8.14@1937.01,624.02
NetR196_1: R196.1 U8.13 | length 62.8
  BottomLayer - S8 (.GBL) w4.92: R196.1@1890.75,674.02 1909.25,655.51 1909.45,655.51 1921.26,643.7 U8.13@1921.26,624.02
NetR197_1: R197.1 U8.12 | length 163
  BottomLayer - S8 (.GBL) w4.92: R197.1@1839.57,674.02 1839.57,615.16 1863.19,591.54 1898.62,591.54 1905.51,598.43 U8.12@1905.51,624.02
NetR198_1: R198.1 U8.11 | length 60.2
  BottomLayer - S8 (.GBL) w4.92: R198.1@1865.16,674.02 1869.09,670.08 1869.09,664.37 1889.76,643.7 U8.11@1889.76,624.02
NetR199_1: R199.1 U9.18 | length 68
  BottomLayer - S8 (.GBL) w4.68: U9.18@1704.72,795.28 1725.2,795.28 1744.88,775.59 R199.1@1764.57,775.59
NetR200_1: R200.1 U9.17 | length 73.8
  BottomLayer - S8 (.GBL) w4.68: U9.17@1694.88,811.02 1738.19,811.02 1748.03,801.18 R200.1@1764.57,801.18
NetR201_1: R201.1 U9.16 | length 69.7
  BottomLayer - S8 (.GBL) w4.68: U9.16@1694.88,826.77 R201.1@1764.57,826.77
NetR202_1: R202.1 U9.15 | length 73.8
  BottomLayer - S8 (.GBL) w4.68: U9.15@1694.88,842.52 1742.13,842.52 1751.97,852.36 R202.1@1764.57,852.36
NetR203_1: R203.1 U9.14 | length 153.5
  BottomLayer - S8 (.GBL) w4.92: R203.1@1625.2,954.72 1621.06,950.59 1621.06,889.76 1652.56,858.27 U9.14@1694.88,858.27
NetR204_1: R204.1 U9.13 | length 71.3
  BottomLayer - S8 (.GBL) w4.68: U9.13@1694.88,874.02 1733.27,874.02 1737.2,877.95 R204.1@1764.57,877.95
NetR205_1: R205.1 U9.12 | length 75.4
  BottomLayer - S8 (.GBL) w4.68: U9.12@1694.88,889.76 1724.41,889.76 1738.19,903.54 R205.1@1764.57,903.54
NetR206_1: R206.1 U9.11 | length 101.7
  BottomLayer - S8 (.GBL) w4.68: U9.11@1675.2,905.51 U9.11@1694.88,905.51 1714.57,905.51 1714.57,948.82 1708.66,954.72 R206.1@1698.03,954.72
NetR207_2: R207.2 U11.B18 | length 53.4
  TopLayer - S1 (.GTL) w4.92: v1(940.94,1633.86) U11.B18@956.69,1618.11
  BottomLayer - S8 (.GBL) w5.91: v1(940.94,1633.86) 940.94,1608.27 R207.2@944.88,1604.33
NetR208_2: R208.2 U11.C15 | length 62.8
  TopLayer - S1 (.GTL) w4.92: v1@972.44,1538.39 973.43,1538.39 U11.C15@988.19,1523.62
  BottomLayer - S8 (.GBL) w5.91: R208.2@944.88,1568.9 944.88,1566.93 v1(972.44,1539.37)
NetR209_1: R209.1 U11.U5 | length 403.5
  TopLayer - S1 (.GTL) w4.92: v1@1415.35,1222.44 U11.U5@1429.13,1208.66
  MidLayer2 - S3 (.G2) w4.92: v1(1413.39,1224.41) 1418.04,1224.41 1433.3,1239.67 1549.7,1239.67 1652.56,1136.81 1652.56,1092.52 v1(1634.84,1074.8)
  BottomLayer - S8 (.GBL) w4.92: v1(1634.84,1074.8) R209.1@1661.42,1074.8
NetR210_1: R210.1 U11.R5 | length 530.4
  TopLayer - S1 (.GTL) w4.92: U11.R5@1366.14,1208.66 v1(1381.89,1192.91) v1@1382.87,1192.91
  MidLayer2 - S3 (.G2) w4.92: v1(1381.89,1192.91) 1397.64,1208.66 1397.64,1233.27 1404.53,1240.16 1421.26,1240.16 1430.12,1249.02 1558.07,1249.02 1665.35,1141.73 1665.35,1069.88 v1(1634.84,1039.37)
  BottomLayer - S8 (.GBL) w4.92: v1(1634.84,1039.37) R210.1@1661.42,1039.37
NetR211_2: R211.2 U11.U12 | length 154.9
  TopLayer - S1 (.GTL) w4.92: U11.U12@1429.13,1429.13 1444.88,1413.39 1501.97,1413.39 1527.56,1438.98 R211.2@1566.93,1438.98
NetR222_2: R222.2 T1.10 | length 96.7
  TopLayer - S1 (.GTL) w11.81: v1(2690.94,573.82) T1.10@2737.4,573.82
  BottomLayer - S8 (.GBL) w11.81: v1(2690.94,573.82) R222.2@2690.94,624.02
NetR223_2: R223.2 T1.15 | length 96.7
  TopLayer - S1 (.GTL) w11.81: v1(2690.94,823.82) T1.15@2737.4,823.82
  BottomLayer - S8 (.GBL) w11.81: R223.2@2690.94,773.62 v1(2690.94,823.82)
NetR226_2: R226.2 T2.10 | length 96.7
  TopLayer - S1 (.GTL) w11.81: v1(2690.94,1380.91) T2.10@2737.4,1380.91
  BottomLayer - S8 (.GBL) w11.81: v1(2690.94,1380.91) R226.2@2690.94,1431.1
NetR227_2: R227.2 T2.15 | length 96.7
  TopLayer - S1 (.GTL) w11.81: v1(2690.94,1630.91) T2.15@2737.4,1630.91
  BottomLayer - S8 (.GBL) w11.81: R227.2@2690.94,1580.71 v1(2690.94,1630.91)
NetR228_2: R228.2 U11.B7 | length 175.7
  TopLayer - S1 (.GTL) w4.92: R228.2@818.11,1198.82 866.14,1198.82 889.76,1222.44 889.76,1234.25 911.42,1255.91 940.94,1255.91 U11.B7@956.69,1271.65
NetR229_2: R229.2 U11.A7 | length 143.7
  TopLayer - S1 (.GTL) w4.92: R229.2@818.11,1226.38 833.66,1226.38 845.47,1214.57 865.16,1214.57 876.97,1226.38 876.97,1240.16 908.46,1271.65 U11.A7@925.2,1271.65
NetR230_2: R230.2 U11.C8 | length 256.2
  TopLayer - S1 (.GTL) w4.92: R230.2@818.11,1171.26 837.6,1171.26 851.38,1185.04 870.08,1185.04 v1(909.45,1224.41) ; v1(972.44,1318.9) U11.C8@988.19,1303.15
  MidLayer5 - S6 (.G5) w4.92: v1(909.45,1224.41) 909.45,1255.91 v1(972.44,1318.9)
NetR231_2: R231.2 U11.B8 | length 159
  TopLayer - S1 (.GTL) w4.92: R231.2@818.11,1253.94 833.66,1253.94 846.46,1266.73 884.84,1266.73 905.51,1287.4 940.94,1287.4 U11.B8@956.69,1303.15
NetR232_2: R232.2 U11.A8 | length 120.9
  TopLayer - S1 (.GTL) w4.92: R232.2@818.11,1336.61 833.66,1336.61 845.47,1324.8 879.92,1324.8 901.57,1303.15 U11.A8@925.2,1303.15
NetR233_2: R233.2 U11.C9 | length 196.6
  TopLayer - S1 (.GTL) w4.92: R233.2@818.11,1364.17 818.11,1362.01 819.88,1360.24 827.76,1360.24 853.35,1334.65 892.72,1334.65 908.46,1350.39 972.44,1350.39 U11.C9@988.19,1334.65
NetR234_2: R234.2 U11.C18 | length 235.7
  TopLayer - S1 (.GTL) w4.92: R234.2@816.93,1740.16 816.93,1716.54 871.06,1662.4 943.9,1662.4 U11.C18@988.19,1618.11
PHY1_CLKOUT: R54.1 R74.2 | length 702.8
  TopLayer - S1 (.GTL) w4.92: R54.1@1757.87,905.51 v1(1757.87,946.85)
  BottomLayer - S8 (.GBL) w4.92: v1(1757.87,946.85) 1783.46,972.44 1783.46,1217.52 1758.86,1242.13 1758.86,1348.43 1771.65,1361.22 1771.65,1538.39 1782.48,1549.21 R74.2@1811.02,1549.21
PHY1_COL: R52.1 U11.T10 | length 1046.2
  TopLayer - S1 (.GTL) w4.92: U11.T10@1397.64,1366.14 v1(1413.39,1350.39) ; v1(1789.37,753.94) 1789.37,779.53 R52.1@1793.31,779.53
  MidLayer2 - S3 (.G2) w4.92: v1(1413.39,1350.39) 1494.09,1269.68 1567.91,1269.68 1687.99,1149.61 1763.78,1149.61 1898.62,1014.76 1898.62,777.56 1858.27,737.2 1806.1,737.2 v1(1789.37,753.94)
PHY1_CRS: R53.1 U3.27 U11.V5 | length 666.5
  TopLayer - S1 (.GTL) w4.92: v1(1444.88,1192.91) U11.V5@1460.63,1208.66 ; v1(1820.87,883.86) 1820.87,899.61 1860.24,899.61 1864.17,895.67 U3.27@1877.95,895.67
  MidLayer2 - S3 (.G2) w4.68: v1(1444.88,1192.91) 1462.6,1175.2 1477.36,1175.2 1566.93,1085.63 1566.93,973.43 1638.78,901.57 1803.15,901.57 v1(1820.87,883.86)
PHY1_LED0: R20.2 R188.2 U3.17 | length 1021.8
  TopLayer - S1 (.GTL) w4.92: R20.2@1537.4,720.47 v1(1537.4,747.05) R188.2@1537.4,769.68 ; U3.17@2041.34,960.63 2041.34,966.54 2047.24,972.44 v1(2097.44,972.44)
  MidLayer5 - S6 (.G5) w4.92: v1@1537.4,745.08 1605.31,677.17 1702.56,677.17 1738.58,641.14 2038.78,641.14 2099.41,701.77 2099.41,930.12 2107.28,937.99 2107.28,962.6 v1(2097.44,972.44)
PHY1_LED1: R21.2 R235.2 U3.24 U10.C2 | length 1032
  TopLayer - S1 (.GTL) w4.92: U10.C2@1612.2,891.73 1612.2,882.87 1622.05,873.03 1622.05,814.96 1655.51,781.5 1681.1,781.5 R235.2@1688.98,773.62 ; R21.2@1685.04,720.47 v1(1685.04,746.06) R235.2@1685.04,773.62 ; v1(1882.87,968.5) 1903.54,968.5 U3.24@1903.54,960.63
  MidLayer5 - S6 (.G5) w4.92: v1(1685.04,746.06) 1754.72,676.38 2023.82,676.38 2059.06,711.61 2059.06,857.28 1947.83,968.5 v1(1882.87,968.5)
PHY1_LED2: R22.2 R51.1 R161.1 | length 1156.7
  TopLayer - S1 (.GTL) w4.92: R22.2@1757.87,720.47 v1(1757.87,753.94) R51.1@1757.87,771.65
  MidLayer2 - S3 (.G2) w4.92: v1(1737.2,1399.61) 1737.2,1207.68 1909.45,1035.43 1909.45,768.7 1895.67,754.92 1895.67,712.6 1881.89,698.82 1823.82,698.82 1800.2,722.44 1789.37,722.44 v1(1757.87,753.94)
  BottomLayer - S8 (.GBL) w4.92: R161.1@1566.93,1411.42 1725.39,1411.42 v1(1737.2,1399.61)
PHY1_RD_N: C31.2 R45.1 T1.8 U3.9 U4.5 U4.6 | length 624.4
  TopLayer - S1 (.GTL) w3.98: U3.9@2066.93,797.24 2074.8,797.24 2078.43,800.87 2084.96,800.87 2096.77,789.06 2107.58,789.06 2114.15,782.48 v1(2116.14,782.48) v1@2118.11,780.51 ; R45.1@2134.84,780.51 R45.1@2141.73,773.62 ; v1@2239.19,656.5 v1(2237.2,656.5) 2241.93,661.22 U4.6@2304.92,661.22 ; U4.6@2305.12,661.42 2306.77,663.07 2317.17,663.07 2323.62,656.62 2323.62,582.8 2339.02,567.4 2355.71,567.4 2363.19,559.92 2363.19,544.29 2371.06,536.42 2398.62,536.42 T1.8@2411.22,523.82
  TopLayer - S1 (.GTL) w4.92: v1@2118.11,780.51 R45.1@2134.84,780.51
  MidLayer2 - S3 (.G2) w3.98: v1(2116.14,782.48) 2118.11,782.48 2124.78,789.15 2141.37,789.15 2151.14,779.38 2151.14,692.57 2180.54,663.17 2228.56,663.17 2235.24,656.5 v1(2237.2,656.5)
  BottomLayer - S8 (.GBL) w7.87: v1(2237.2,656.5) C31.2@2255.91,656.5
PHY1_RD_P: C30.2 R44.1 T1.6 U3.10 U4.4 U4.7 | length 619.6
  TopLayer - S1 (.GTL) w3.98: U3.10@2066.93,816.93 2074.8,816.93 2078.43,813.31 2090.11,813.31 2101.93,801.5 2107.58,801.5 2114.15,808.07 v1(2116.14,808.07) ; R44.1@2140.75,808.07 R44.1@2141.73,809.06 ; v1(2237.2,682.09) 2241.93,677.36 U4.7@2304.92,677.36 ; U4.7@2305.12,677.17 2306.77,675.51 2322.32,675.51 2336.06,661.77 2336.06,587.95 2344.17,579.84 2355.71,579.84 2363.19,587.32 2363.19,603.35 2371.06,611.22 2398.62,611.22 T1.6@2411.22,623.82
  TopLayer - S1 (.GTL) w4.92: v1(2116.14,808.07) R44.1@2140.75,808.07
  MidLayer2 - S3 (.G2) w3.98: v1(2116.14,808.07) 2118.11,808.07 2124.78,801.4 2146.44,801.4 2163.39,784.45 2163.39,697.64 2185.61,675.41 2228.56,675.41 2235.24,682.09 v1(2237.2,682.09)
  BottomLayer - S8 (.GBL) w7.87: v1(2237.2,682.09) C30.2@2255.91,682.09
PHY1_RJ_RD_N: J6.6 T1.9 | length 516.7
  TopLayer - S1 (.GTL) w3.98: T1.9@2746.26,523.82 2758.86,536.42 2782.48,536.42 2813.66,567.6 2923.9,567.6 3028.54,672.24 3107.28,672.24 3125,654.53 3125,629.92 3119.09,624.02 3112.2,624.02 J6.6@3086.61,638.19
PHY1_RJ_RD_P: J6.3 T1.11 | length 516.7
  TopLayer - S1 (.GTL) w3.98: T1.11@2746.26,623.82 2758.86,611.22 2782.48,611.22 2813.66,580.04 2918.74,580.04 3023.39,684.69 3106.93,684.69 3125.98,703.74 3125.98,727.95 J6.3@3156.69,758.66
PHY1_RJ_TD_N: J6.2 T1.14 | length 516.6
  TopLayer - S1 (.GTL) w3.98: T1.14@2746.26,773.82 2758.86,786.42 2782.48,786.42 2813.66,817.6 2838.04,817.6 2893.47,762.17 2927.52,762.17 3035.79,870.43 3068.54,870.43 3116.14,822.83 3116.14,815.94 J6.2@3086.61,798.82
PHY1_RJ_TD_P: J6.1 T1.16 | length 516.5
  TopLayer - S1 (.GTL) w3.98: T1.16@2746.26,873.82 2758.86,861.22 2782.48,861.22 2813.66,830.04 2843.19,830.04 2898.62,774.61 2922.37,774.61 3030.63,882.87 3073.7,882.87 3121.93,834.65 ; 3122.05,834.65 J6.1@3156.69,838.98
PHY1_RXCLK: U3.25 U10.B1 | length 379.8
  TopLayer - S1 (.GTL) w4.92: U10.B1@1631.89,911.42 1631.89,923.23 v1(1640.75,932.09) ; v1(1852.36,946.85) 1852.36,946.21 1863.53,935.04 U3.25@1877.95,935.04
  MidLayer2 - S3 (.G2) w4.68: v1(1640.75,932.09) 1658.46,914.37 1687.01,914.37 ccw(c1687.01,923.23) 1695.87,923.23 1695.87,934.09 cw(c1704.72,934.09) 1704.72,942.95 cw(c1704.72,934.09) 1713.58,934.09 1713.58,923.23 ccw(c1722.44,923.23) 1722.44,914.37 ccw(c1722.44,923.23) 1731.3,923.23 1731.3,923.73 cw(c1740.16,923.73) 1740.16,932.59 cw(c1740.16,923.73) 1749.02,923.73 1749.02,923.23 ccw(c1757.87,923.23) 1757.87,914.37 1760.59,914.37 ccw(c1760.59,920.52) 1766.73,920.52 cw(c1775.59,920.52) 1775.59,929.37 cw(c1775.59,920.52) 1784.45,920.52 ccw(c1790.59,920.52) 1790.59,914.37 1807.09,914.37 1812.01,914.37 ; 1819.88,922.24 1819.88,937.99 ; 1828.74,946.85 v1(1852.36,946.85)
  MidLayer2 - S3 (.G2) w4.92: 1812.01,914.37 ccw(c1812.01,922.24) 1819.88,922.24 ; 1819.88,937.99 cw(c1828.74,937.99) 1828.74,946.85
PHY1_RXD0: R202.2 U3.30 U11.U4 | length 1001.2
  TopLayer - S1 (.GTL) w4.92: U11.U4@1429.13,1177.17 v1(1444.88,1161.42) ; v1(1852.36,836.61) U3.30@1877.95,836.61
  MidLayer2 - S3 (.G2) w4.68: v1(1444.88,1161.42) 1471.46,1161.42 cw(c1471.46,1153.54) 1479.33,1153.54 cw(c1471.46,1153.54) 1471.46,1145.67 1468.5,1145.67 ccw(c1468.5,1137.8) 1460.63,1137.8 1460.63,1121.85 1468.31,1114.17 1500,1114.17 1539.37,1074.8 1539.37,932.09 1575.79,895.67 1585.63,895.67 1605.31,875.98 1614.17,875.98 cw(c1614.17,867.13) 1623.03,867.13 1623.03,859.63 ccw(c1631.89,859.63) 1631.89,850.77 ccw(c1631.89,859.63) 1640.75,859.63 1640.75,867.13 cw(c1649.61,867.13) 1649.61,875.98 cw(c1649.61,867.13) 1658.46,867.13 1658.46,859.63 ccw(c1667.32,859.63) 1667.32,850.77 ccw(c1667.32,859.63) 1676.18,859.63 1676.18,867.13 cw(c1685.04,867.13) 1685.04,875.98 cw(c1685.04,867.13) 1693.9,867.13 1693.9,859.63 ccw(c1702.76,859.63) 1702.76,850.77 ccw(c1702.76,859.63) 1711.61,859.63 1711.61,867.13 cw(c1720.47,867.13) 1720.47,875.98 1744.09,875.98 cw(c1744.09,867.13) 1752.95,867.13 1752.95,865.07 ccw(c1761.81,865.07) 1761.81,856.21 ccw(c1761.81,865.07) 1770.67,865.07 1770.67,867.13 cw(c1779.53,867.13) 1779.53,875.98 1784.45,875.98 1806.1,854.33 1862.2,854.33 cw(c1862.2,846.46) 1870.08,846.46 1870.08,824.8 cw(c1862.2,824.8) 1862.2,816.93 1860.24,816.93 cw(c1860.24,824.8) 1852.36,824.8 v1(1852.36,836.61)
  BottomLayer - S8 (.GBL) w4.92: R202.2@1786.61,852.36 1836.61,852.36 v1(1852.36,836.61)
PHY1_RXD1: R201.2 U3.31 U11.U3 | length 967.9
  TopLayer - S1 (.GTL) w4.92: U11.U3@1429.13,1145.67 v1(1444.88,1129.92) ; v1(1820.87,836.61) 1840.55,816.93 U3.31@1877.95,816.93
  MidLayer2 - S3 (.G2) w4.68: v1(1444.88,1129.92) 1444.88,1121.06 1461.12,1104.82 1461.12,1092.11 1470.06,1083.17 1485.73,1083.17 1497.05,1071.85 1497.05,1069.88 1497.05,1062.01 cw(c1488.19,1062.01) 1488.48,1053.15 ; v1(1820.87,836.61) 1609.25,836.61 1589.57,856.3 1557.09,856.3 1552.17,861.22 ccw(c1545.9,854.96) 1539.64,861.22 1538.57,860.15 cw(c1532.3,866.41) 1526.04,860.15 cw(c1532.3,866.41) 1526.04,872.68 1533.37,880.01 1539.23,885.87 ccw(c1532.97,892.13) 1539.23,898.4 ccw(c1532.97,892.13) 1526.71,898.4 1520.85,892.54 1513.51,885.2 cw(c1507.25,891.47) 1500.98,885.2 cw(c1507.25,891.47) 1500.98,897.73 1502.06,898.8 ccw(c1495.79,905.07) 1502.06,911.33 1499.51,913.88 1497.05,916.34 1497.05,920.28 ccw(c1488.19,920.28) 1488.19,929.13 cw(c1488.19,937.99) 1479.33,937.99 cw(c1488.19,937.99) 1488.19,946.85 1497.05,946.85 1501.62,946.85 ccw(c1501.62,955.71) 1510.48,955.71 ccw(c1501.62,955.71) 1501.62,964.57 1497.05,964.57 1488.53,964.57 cw(c1488.53,973.43) 1479.67,973.43 cw(c1488.53,973.43) 1488.53,982.28 1497.05,982.28 1501.62,982.28 ccw(c1501.62,991.14) 1510.48,991.14 ccw(c1501.62,991.14) 1501.62,1000 1497.05,1000 1488.53,1000 cw(c1488.53,1008.86) 1479.67,1008.86 cw(c1488.53,1008.86) 1488.53,1017.72 1497.05,1017.72 1501.62,1017.72 ccw(c1501.62,1026.58) 1510.48,1026.58 ccw(c1501.62,1026.58) 1501.62,1035.43 1497.05,1035.43 1488.53,1035.43 cw(c1488.53,1044.29) 1479.67,1044.29 cw(c1488.53,1044.29) 1488.24,1053.15 ; 1488.24,1053.15 ccw(c1488.19,1062.01) 1488.48,1053.15 ; 1488.24,1053.15 cw(c1488.53,1044.29) 1488.48,1053.15 ; 1488.24,1053.15 1488.48,1053.15
  BottomLayer - S8 (.GBL) w4.92: R201.2@1786.61,826.77 1811.02,826.77 v1(1820.87,836.61)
